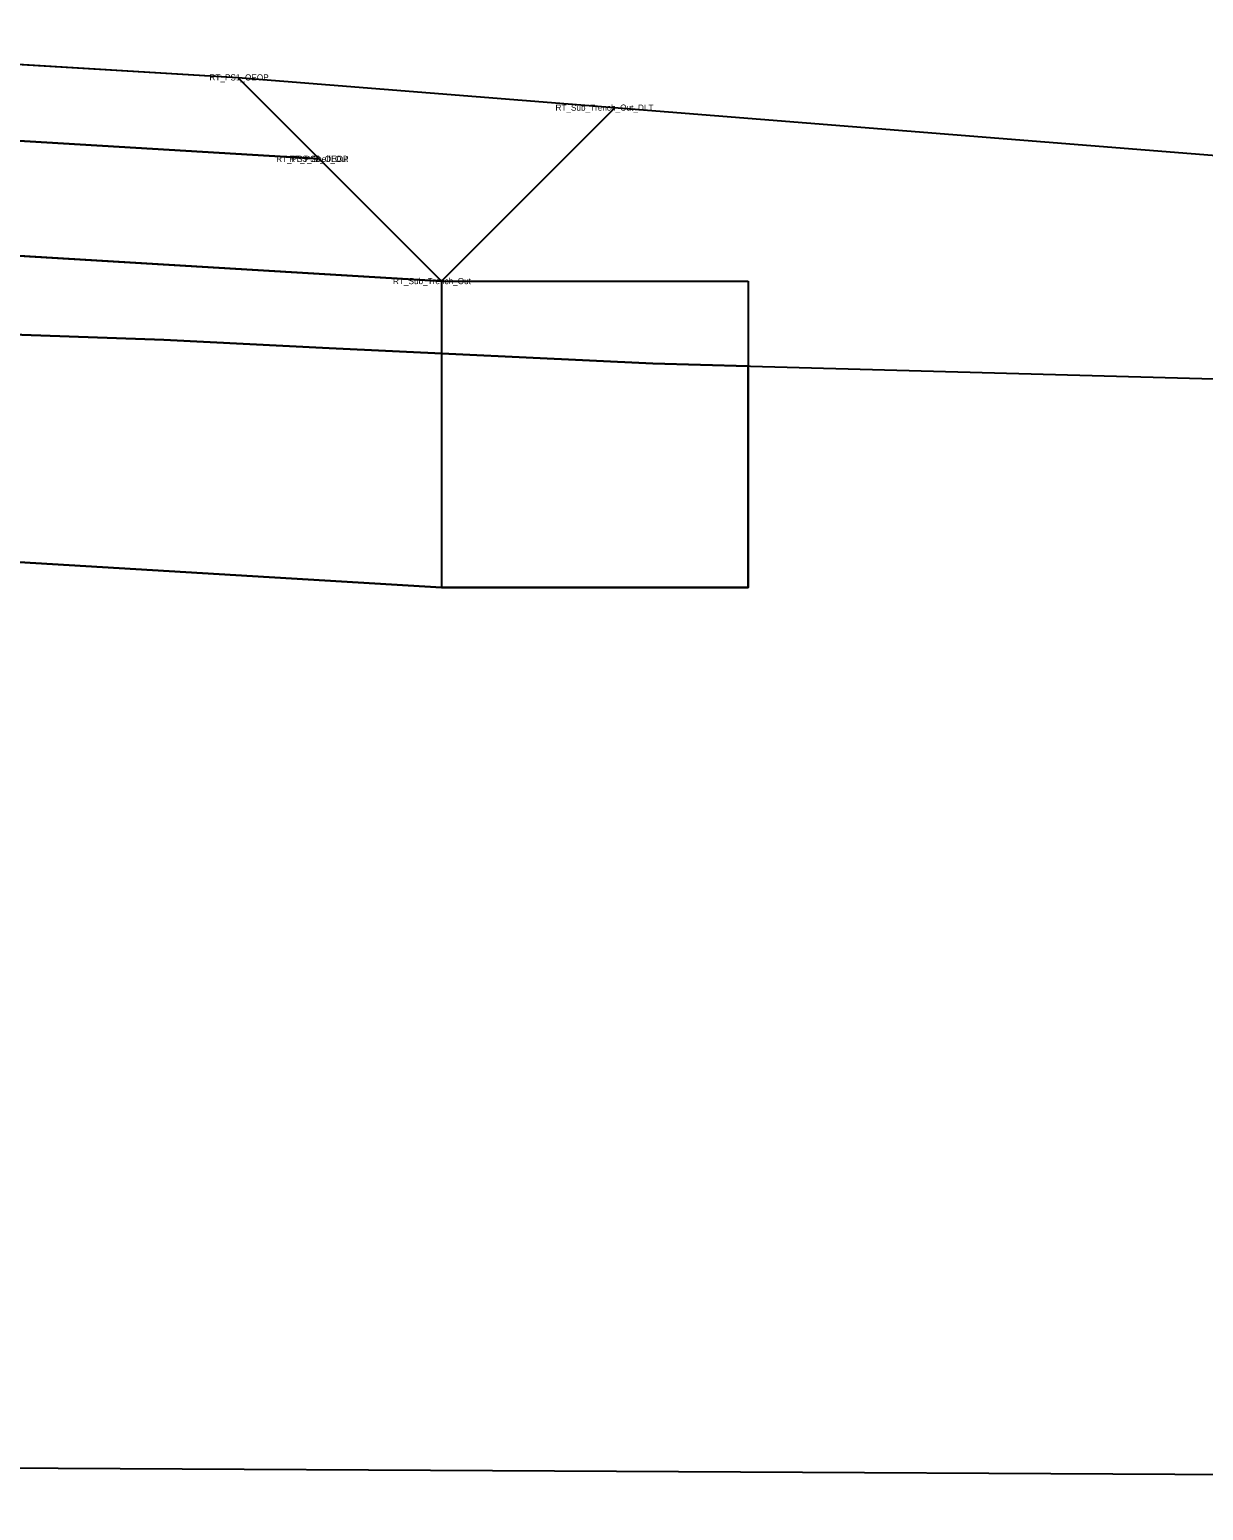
# Model space of a CAD drawing. Extents: x -516 to 303, y -10 to 5017.
# Drawn here: x 163.921 to 167.75, y 2003.593 to 2008.426 of the extents above; entities that cross this region are included whole.
import ezdxf

# ---------------------------------------------------------------- set-up
doc = ezdxf.new("R2010")
doc.units = 0
for name, color, linetype in [('Exist XS Ground Line', 7, 'Continuous'), ('Prop CMT Pvmt Surface Shoulder', 7, 'Continuous'), ('Prop CMT Shld Paved Course 1', 7, 'Continuous'), ('Prop CMT Shld Paved Course 2', 7, 'Continuous'), ('Prop CMT Shld Paved Course 3', 7, 'Continuous'), ('Prop CMT Slope Grass', 7, 'Continuous'), ('Prop CMT Subgrade Earthwork', 7, 'Continuous'), ('Prop Road Sect_ Material - Contact (General - Major)', 7, 'Continuous'), ('Prop Road Sect_ Misc - Drafting Aid (solid line)', 7, 'Continuous'), ('Prop Road Sect_ Recs - UC Shallow (Outline)', 7, 'Continuous'), ('Prop Road Sect_ Recs - UC Shallow (Pattern)', 7, 'Continuous'), ('Scratch_Level_0', 7, 'Continuous')]:
    doc.layers.add(name, color=color, linetype=linetype)

msp = doc.modelspace()

# ---------------------------------------------------------------- linework, layer by layer
at = {"layer": 'Exist XS Ground Line'}
msp.add_lwpolyline([(158.4835, 2007.6479), (159.961, 2007.5813), (161.0579, 2007.5364), (161.7106, 2007.5109), (163.7403, 2007.435), (164.3584, 2007.4133), (164.8981, 2007.3863), (165.9538, 2007.3364), (168.7402, 2007.2595), (171.8286, 2007.0285), (177.0448, 2006.6472)], dxfattribs=at)
at = {"layer": 'Prop CMT Pvmt Surface Shoulder'}
msp.add_line((162, 2008.4261), (164.6, 2008.2701), dxfattribs=at)
at = {"layer": 'Prop CMT Shld Paved Course 1'}
for points in [[(162, 2008.4261), (164.6, 2008.2701), (164.866, 2008.0041)], [(164.866, 2008.0041), (162, 2008.1761)]]:
    msp.add_lwpolyline(points, dxfattribs=at)
at = {"layer": 'Prop CMT Shld Paved Course 2'}
for points in [[(162, 2008.1761), (164.866, 2008.0041)], [(164.866, 2008.0041), (162, 2008.1761)], [(164.866, 2008.0041), (164.866, 2008.0041)]]:
    msp.add_lwpolyline(points, dxfattribs=at)
at = {"layer": 'Prop CMT Shld Paved Course 3'}
for points in [[(162, 2008.1761), (164.866, 2008.0041)], [(164.866, 2008.0041), (164.866, 2008.0041)], [(164.866, 2008.0041), (165.2649, 2007.6052)], [(165.2649, 2007.6052), (162, 2007.8011)]]:
    msp.add_lwpolyline(points, dxfattribs=at)
at = {"layer": 'Prop CMT Slope Grass'}
msp.add_line((164.6, 2008.2701), (170, 2007.8381), dxfattribs=at)
at = {"layer": 'Prop CMT Subgrade Earthwork'}
for p, q in [((165.2649, 2007.6052), (165.8313, 2008.1715)), ((162, 2007.8011), (165.2649, 2007.6052))]:
    msp.add_line(p, q, dxfattribs=at)
at = {"layer": 'Prop Road Sect_ Material - Contact (General - Major)'}
msp.add_line((33.3727, 2004.4513), (189.0466, 2003.5926), dxfattribs=at)
at = {"layer": 'Prop Road Sect_ Misc - Drafting Aid (solid line)'}
for p, q in [((165.2649, 2007.6052), (166.2649, 2007.6052)), ((165.2649, 2007.6052), (165.2649, 2006.6052)), ((166.2649, 2007.6052), (166.2649, 2006.6052)), ((165.2649, 2006.6052), (162, 2006.8011)), ((166.2649, 2006.6052), (165.2649, 2006.6052))]:
    msp.add_line(p, q, dxfattribs=at)
at = {"layer": 'Prop Road Sect_ Recs - UC Shallow (Outline)'}
msp.add_lwpolyline([(148, 2007.6411), (148, 2007.9593), (148.2019, 2007.9549), (149.3973, 2007.9221), (150, 2007.906), (150.7755, 2007.8854), (153.3472, 2007.8082), (154.1183, 2007.7912), (155.9076, 2007.7453), (157.6019, 2007.6791), (158.4835, 2007.6479), (159.961, 2007.5813), (161.0579, 2007.5364), (161.7106, 2007.5109), (163.7403, 2007.435), (164.3584, 2007.4133), (164.8981, 2007.3863), (165.9538, 2007.3364), (166.2649, 2007.3278), (166.2649, 2006.6052), (165.2649, 2006.6052), (162, 2006.8011)], close=True, dxfattribs=at)
at = {"layer": 'Prop Road Sect_ Recs - UC Shallow (Pattern)'}
msp.add_lwpolyline([(162, 2006.8011), (165.2649, 2006.6052), (166.2649, 2006.6052), (166.2649, 2007.3278), (165.9538, 2007.3364), (164.8981, 2007.3863), (164.3584, 2007.4133), (163.7403, 2007.435), (161.7106, 2007.5109), (161.0579, 2007.5364), (159.961, 2007.5813), (158.4835, 2007.6479), (157.6019, 2007.6791), (155.9076, 2007.7453), (154.1183, 2007.7912), (153.3472, 2007.8082), (150.7755, 2007.8854), (150, 2007.906), (149.3973, 2007.9221), (148.2019, 2007.9549), (148, 2007.9593), (148, 2007.6411), (162, 2006.8011)], dxfattribs=at)

# ---------------------------------------------------------------- texts
at = {"layer": 'Scratch_Level_0'}
for s, p in [('RT_PS1_OEOP', (164.5076, 2008.2601)), ('RT_Sub_Trench_Out_DLT', (165.6365, 2008.1615)), ('RT_PS3_Shelf_Out', (164.7253, 2007.9941)), ('RT_PS3_OEOP', (164.7678, 2007.9941)), ('RT_PS2_OEOP', (164.7678, 2007.9941)), ('RT_Sub_Trench_Out', (165.1065, 2007.5952))]:
    msp.add_text(s, height=0.02, dxfattribs=at).set_placement(p)

doc.saveas('drawing.dxf')
